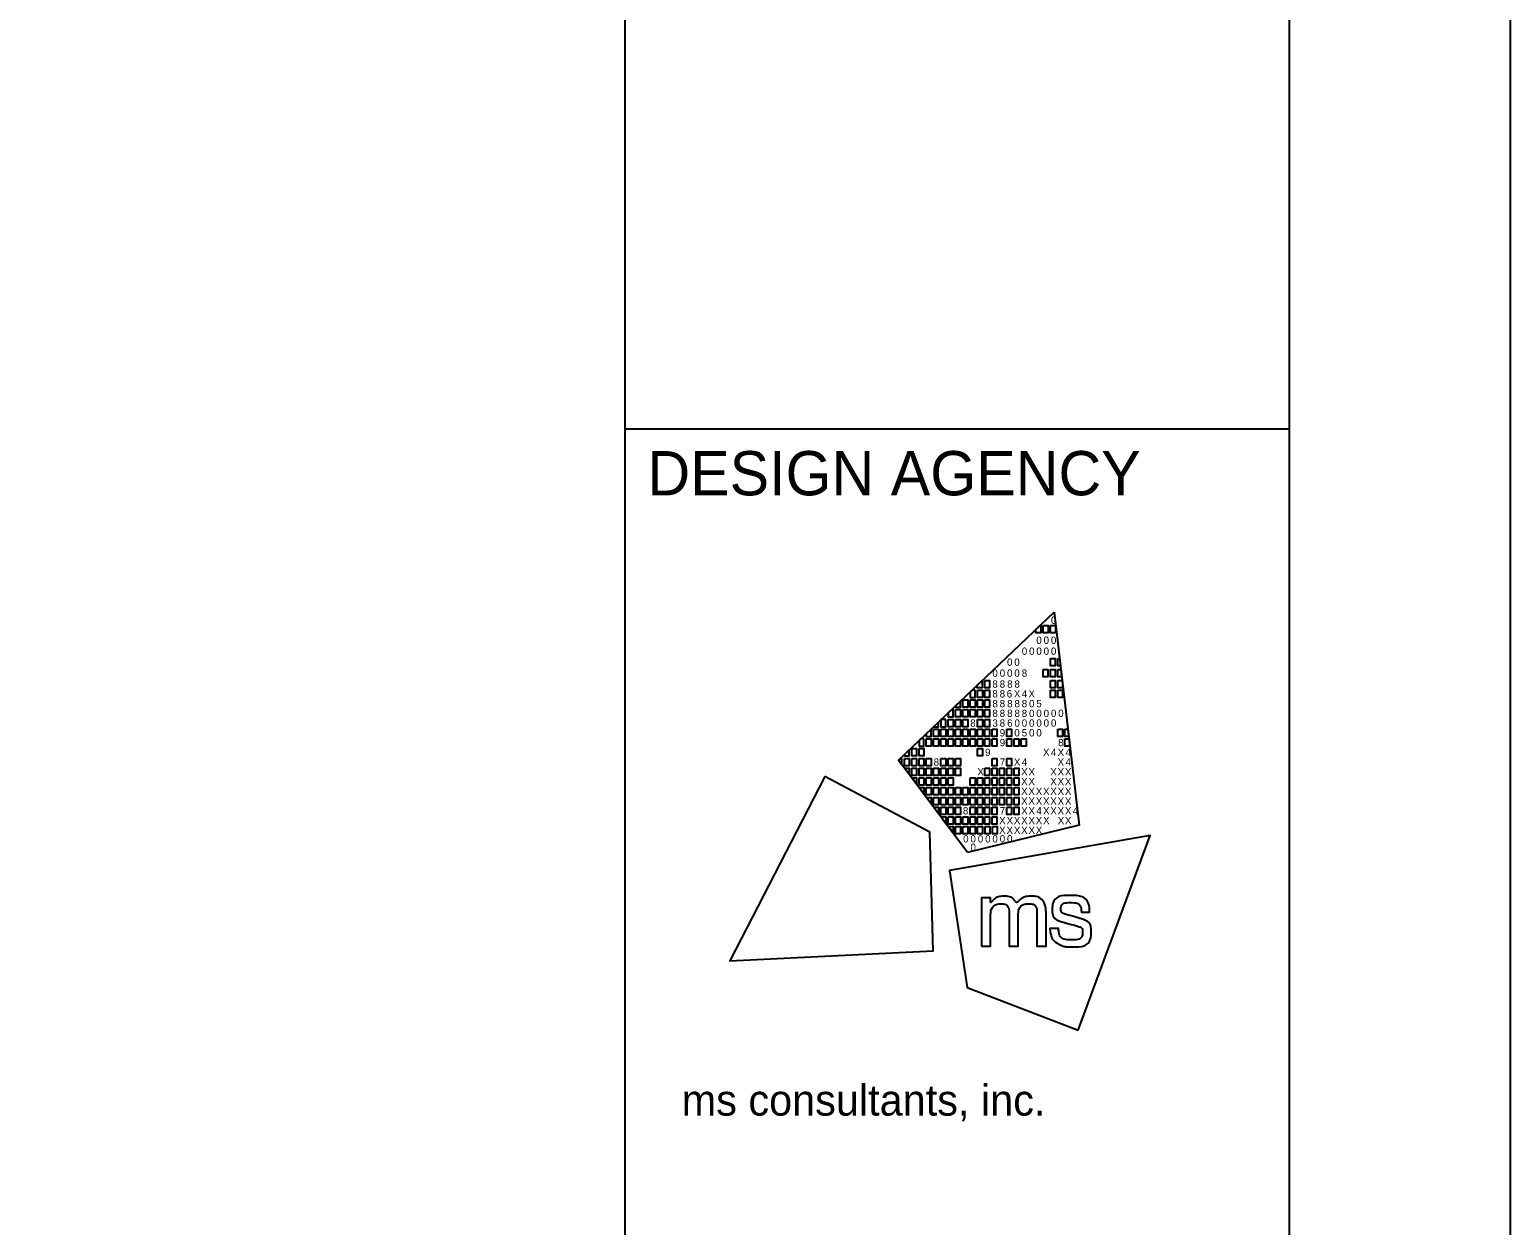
# Model space of a CAD drawing. Extents: x 0 to 680, y 0 to 440.
# Drawn here: x 613.1 to 680, y 54 to 108 of the extents above; entities that cross this region are included whole.
import ezdxf

# ---------------------------------------------------------------- set-up
doc = ezdxf.new("R2010")
doc.units = 0
for name, color, linetype in [('Default', 7, 'Continuous'), ('SH_Border', 7, 'Continuous'), ('SH_Cut_Line', 7, 'Continuous'), ('SH_Data', 7, 'Continuous')]:
    doc.layers.add(name, color=color, linetype=linetype)

msp = doc.modelspace()

# ---------------------------------------------------------------- linework, layer by layer
at = {"layer": 'Default'}
for p, q in [((652.351, 75.039), (659.376, 81.722)), ((659.376, 81.722), (659.376, 81.722)), ((659.376, 81.722), (660.506, 72.103)), ((655.461, 70.86), (652.351, 75.039)), ((660.506, 72.103), (655.461, 70.86))]:
    msp.add_line(p, q, dxfattribs=at)
for points in [[(658.559, 80.945), (658.738, 81.116), (658.779, 81.116), (658.779, 80.785), (658.559, 80.785)], [(658.888, 81.116), (659.109, 81.116), (659.109, 80.785), (658.888, 80.785)], [(659.219, 81.116), (659.439, 81.116), (659.439, 80.785), (659.219, 80.785)], [(658.883, 79.134), (659.103, 79.134), (659.103, 78.804), (658.883, 78.804)], [(659.212, 79.629), (659.433, 79.629), (659.433, 79.299), (659.212, 79.299)], [(659.212, 79.134), (659.433, 79.134), (659.433, 78.804), (659.212, 78.804)], [(659.542, 79.629), (659.622, 79.629), (659.661, 79.299), (659.542, 79.299)], [(659.542, 79.134), (659.68, 79.134), (659.719, 78.804), (659.542, 78.804)], [(655.908, 78.422), (656.128, 78.632), (656.128, 78.308), (655.908, 78.308)], [(656.246, 78.639), (656.466, 78.639), (656.466, 78.308), (656.246, 78.308)], [(659.212, 78.639), (659.433, 78.639), (659.433, 78.308), (659.212, 78.308)], [(659.542, 78.639), (659.738, 78.639), (659.762, 78.437), (659.762, 78.308), (659.542, 78.308)], [(655.255, 77.758), (655.476, 77.758), (655.476, 77.428), (655.255, 77.428)], [(655.586, 77.758), (655.806, 77.758), (655.806, 77.428), (655.586, 77.428)], [(655.916, 78.198), (656.136, 78.198), (656.136, 77.868), (655.916, 77.868)], [(655.916, 77.758), (656.136, 77.758), (656.136, 77.428), (655.916, 77.428)], [(656.246, 78.198), (656.466, 78.198), (656.466, 77.868), (656.246, 77.868)], [(656.246, 77.758), (656.466, 77.758), (656.466, 77.428), (656.246, 77.428)], [(659.212, 78.198), (659.433, 78.198), (659.433, 77.868), (659.212, 77.868)], [(659.542, 78.198), (659.762, 78.198), (659.762, 77.868), (659.542, 77.868)], [(654.925, 77.318), (655.145, 77.318), (655.145, 76.987), (654.925, 76.987)], [(655.255, 77.318), (655.476, 77.318), (655.476, 76.987), (655.255, 76.987)], [(655.586, 77.318), (655.806, 77.318), (655.806, 76.987), (655.586, 76.987)], [(655.916, 77.318), (656.136, 77.318), (656.136, 76.987), (655.916, 76.987)], [(656.246, 77.318), (656.466, 77.318), (656.466, 76.987), (656.246, 76.987)], [(653.934, 76.437), (654.154, 76.437), (654.154, 76.107), (653.934, 76.107)], [(654.265, 76.437), (654.485, 76.437), (654.485, 76.107), (654.265, 76.107)], [(654.595, 76.877), (654.815, 76.877), (654.815, 76.547), (654.595, 76.547)], [(654.595, 76.437), (654.815, 76.437), (654.815, 76.107), (654.595, 76.107)], [(654.925, 76.877), (655.145, 76.877), (655.145, 76.547), (654.925, 76.547)], [(654.925, 76.437), (655.145, 76.437), (655.145, 76.107), (654.925, 76.107)], [(655.255, 76.877), (655.476, 76.877), (655.476, 76.547), (655.255, 76.547)], [(655.255, 76.437), (655.476, 76.437), (655.476, 76.107), (655.255, 76.107)], [(655.586, 76.437), (655.806, 76.437), (655.806, 76.107), (655.586, 76.107)], [(655.916, 76.877), (656.136, 76.877), (656.136, 76.547), (655.916, 76.547)], [(655.916, 76.437), (656.136, 76.437), (656.136, 76.107), (655.916, 76.107)], [(656.246, 76.877), (656.466, 76.877), (656.466, 76.547), (656.246, 76.547)], [(656.246, 76.437), (656.466, 76.437), (656.466, 76.107), (656.246, 76.107)], [(656.576, 76.437), (656.797, 76.437), (656.797, 76.107), (656.576, 76.107)], [(657.237, 76.437), (657.457, 76.437), (657.457, 76.107), (657.237, 76.107)], [(659.542, 76.437), (659.762, 76.437), (659.762, 76.107), (659.542, 76.107)], [(659.871, 76.437), (659.997, 76.437), (660.036, 76.107), (659.871, 76.107)], [(653.604, 75.996), (653.824, 75.996), (653.824, 75.666), (653.604, 75.666)], [(653.934, 75.996), (654.154, 75.996), (654.154, 75.666), (653.934, 75.666)], [(654.265, 75.996), (654.485, 75.996), (654.485, 75.666), (654.265, 75.666)], [(654.595, 75.996), (654.815, 75.996), (654.815, 75.666), (654.595, 75.666)], [(654.925, 75.996), (655.145, 75.996), (655.145, 75.666), (654.925, 75.666)], [(655.255, 75.996), (655.476, 75.996), (655.476, 75.666), (655.255, 75.666)], [(655.586, 75.996), (655.806, 75.996), (655.806, 75.666), (655.586, 75.666)], [(655.916, 75.996), (656.136, 75.996), (656.136, 75.666), (655.916, 75.666)], [(656.246, 75.996), (656.466, 75.996), (656.466, 75.666), (656.246, 75.666)], [(656.576, 75.996), (656.797, 75.996), (656.797, 75.666), (656.576, 75.666)], [(657.237, 75.996), (657.457, 75.996), (657.457, 75.666), (657.237, 75.666)], [(657.567, 75.996), (657.787, 75.996), (657.787, 75.666), (657.567, 75.666)], [(657.895, 75.996), (658.115, 75.996), (658.115, 75.666), (657.895, 75.666)], [(659.871, 75.996), (660.049, 75.996), (660.088, 75.666), (659.871, 75.666)], [(652.613, 75.116), (652.833, 75.116), (652.833, 74.785), (652.613, 74.785)], [(652.943, 75.556), (653.164, 75.556), (653.164, 75.226), (652.943, 75.226)], [(652.943, 75.116), (653.164, 75.116), (653.164, 74.785), (652.943, 74.785)], [(653.274, 75.556), (653.494, 75.556), (653.494, 75.226), (653.274, 75.226)], [(653.274, 75.116), (653.494, 75.116), (653.494, 74.785), (653.274, 74.785)], [(653.604, 75.116), (653.824, 75.116), (653.824, 74.785), (653.604, 74.785)], [(654.265, 75.116), (654.485, 75.116), (654.485, 74.785), (654.265, 74.785)], [(654.595, 75.116), (654.815, 75.116), (654.815, 74.785), (654.595, 74.785)], [(654.925, 75.116), (655.145, 75.116), (655.145, 74.785), (654.925, 74.785)], [(655.916, 75.556), (656.136, 75.556), (656.136, 75.226), (655.916, 75.226)], [(656.576, 75.116), (656.797, 75.116), (656.797, 74.785), (656.576, 74.785)], [(657.237, 75.116), (657.457, 75.116), (657.457, 74.785), (657.237, 74.785)], [(652.613, 74.675), (652.833, 74.675), (652.833, 74.4)], [(652.943, 74.675), (653.164, 74.675), (653.164, 74.345), (652.943, 74.345)], [(653.274, 74.675), (653.494, 74.675), (653.494, 74.345), (653.274, 74.345)], [(653.604, 74.675), (653.824, 74.675), (653.824, 74.345), (653.604, 74.345)], [(653.934, 74.675), (654.154, 74.675), (654.154, 74.345), (653.934, 74.345)], [(654.265, 74.675), (654.485, 74.675), (654.485, 74.345), (654.265, 74.345)], [(654.595, 74.675), (654.815, 74.675), (654.815, 74.345), (654.595, 74.345)], [(654.925, 74.675), (655.145, 74.675), (655.145, 74.345), (654.925, 74.345)], [(656.246, 74.675), (656.466, 74.675), (656.466, 74.345), (656.246, 74.345)], [(656.576, 74.675), (656.797, 74.675), (656.797, 74.345), (656.576, 74.345)], [(656.907, 74.675), (657.127, 74.675), (657.127, 74.345), (656.907, 74.345)], [(657.237, 74.675), (657.457, 74.675), (657.457, 74.345), (657.237, 74.345)], [(657.567, 74.675), (657.787, 74.675), (657.787, 74.345), (657.567, 74.345)], [(652.943, 74.235), (653.164, 74.235), (653.164, 73.96)], [(653.274, 74.235), (653.494, 74.235), (653.494, 73.905), (653.274, 73.905)], [(653.274, 73.795), (653.494, 73.795), (653.494, 73.519)], [(653.494, 73.795), (653.494, 73.795), (653.494, 73.795)], [(653.604, 74.235), (653.824, 74.235), (653.824, 73.905), (653.604, 73.905)], [(653.604, 73.795), (653.824, 73.795), (653.824, 73.464), (653.604, 73.464)], [(653.934, 74.235), (654.154, 74.235), (654.154, 73.905), (653.934, 73.905)], [(653.934, 73.795), (654.154, 73.795), (654.154, 73.464), (653.934, 73.464)], [(654.265, 74.235), (654.485, 74.235), (654.485, 73.905), (654.265, 73.905)], [(654.265, 73.795), (654.485, 73.795), (654.485, 73.464), (654.265, 73.464)], [(654.595, 74.235), (654.815, 74.235), (654.815, 73.905), (654.595, 73.905)], [(654.595, 73.795), (654.815, 73.795), (654.815, 73.464), (654.595, 73.464)], [(654.925, 73.795), (655.145, 73.795), (655.145, 73.464), (654.925, 73.464)], [(655.255, 73.795), (655.476, 73.795), (655.476, 73.464), (655.255, 73.464)], [(655.586, 74.235), (655.806, 74.235), (655.806, 73.905), (655.586, 73.905)], [(655.586, 73.795), (655.806, 73.795), (655.806, 73.464), (655.586, 73.464)], [(655.916, 74.235), (656.136, 74.235), (656.136, 73.905), (655.916, 73.905)], [(655.916, 73.795), (656.136, 73.795), (656.136, 73.464), (655.916, 73.464)], [(656.246, 74.235), (656.466, 74.235), (656.466, 73.905), (656.246, 73.905)], [(656.246, 73.795), (656.466, 73.795), (656.466, 73.464), (656.246, 73.464)], [(656.576, 74.235), (656.797, 74.235), (656.797, 73.905), (656.576, 73.905)], [(656.576, 73.795), (656.797, 73.795), (656.797, 73.464), (656.576, 73.464)], [(656.907, 74.235), (657.127, 74.235), (657.127, 73.905), (656.907, 73.905)], [(656.907, 73.795), (657.127, 73.795), (657.127, 73.464), (656.907, 73.464)], [(657.237, 74.235), (657.457, 74.235), (657.457, 73.905), (657.237, 73.905)], [(657.237, 73.795), (657.457, 73.795), (657.457, 73.464), (657.237, 73.464)], [(657.567, 74.235), (657.787, 74.235), (657.787, 73.905), (657.567, 73.905)], [(657.567, 73.795), (657.787, 73.795), (657.787, 73.464), (657.567, 73.464)], [(653.604, 73.354), (653.824, 73.354), (653.824, 73.079)], [(653.934, 73.354), (654.154, 73.354), (654.154, 73.024), (653.934, 73.024)], [(654.265, 73.354), (654.485, 73.354), (654.485, 73.024), (654.265, 73.024)], [(654.595, 73.354), (654.815, 73.354), (654.815, 73.024), (654.595, 73.024)], [(654.925, 73.354), (655.145, 73.354), (655.145, 73.024), (654.925, 73.024)], [(655.255, 73.354), (655.476, 73.354), (655.476, 73.024), (655.255, 73.024)], [(655.586, 73.354), (655.806, 73.354), (655.806, 73.024), (655.586, 73.024)], [(655.916, 73.354), (656.136, 73.354), (656.136, 73.024), (655.916, 73.024)], [(656.246, 73.354), (656.466, 73.354), (656.466, 73.024), (656.246, 73.024)], [(656.576, 73.354), (656.797, 73.354), (656.797, 73.024), (656.576, 73.024)], [(656.907, 73.354), (657.127, 73.354), (657.127, 73.024), (656.907, 73.024)], [(657.237, 73.354), (657.457, 73.354), (657.457, 73.024), (657.237, 73.024)], [(657.567, 73.354), (657.787, 73.354), (657.787, 73.024), (657.567, 73.024)], [(654.155, 72.611), (653.931, 72.915), (654.155, 72.915)], [(654.48, 72.164), (654.264, 72.474), (654.484, 72.474)], [(654.265, 72.914), (654.485, 72.914), (654.485, 72.584), (654.265, 72.584)], [(654.595, 72.914), (654.815, 72.914), (654.815, 72.584), (654.595, 72.584)], [(654.595, 72.473), (654.815, 72.473), (654.815, 72.143), (654.595, 72.143)], [(654.925, 72.914), (655.145, 72.914), (655.145, 72.584), (654.925, 72.584)], [(654.925, 72.473), (655.145, 72.473), (655.145, 72.143), (654.925, 72.143)], [(655.255, 72.473), (655.476, 72.473), (655.476, 72.143), (655.255, 72.143)], [(655.586, 72.914), (655.806, 72.914), (655.806, 72.584), (655.586, 72.584)], [(655.586, 72.473), (655.806, 72.473), (655.806, 72.143), (655.586, 72.143)], [(655.916, 72.914), (656.136, 72.914), (656.136, 72.584), (655.916, 72.584)], [(655.916, 72.473), (656.136, 72.473), (656.136, 72.143), (655.916, 72.143)], [(656.246, 72.914), (656.466, 72.914), (656.466, 72.584), (656.246, 72.584)], [(656.246, 72.473), (656.466, 72.473), (656.466, 72.143), (656.246, 72.143)], [(656.576, 72.914), (656.797, 72.914), (656.797, 72.584), (656.576, 72.584)], [(656.576, 72.473), (656.797, 72.473), (656.797, 72.143), (656.576, 72.143)], [(657.237, 72.914), (657.457, 72.914), (657.457, 72.584), (657.237, 72.584)], [(657.567, 72.914), (657.787, 72.914), (657.787, 72.584), (657.567, 72.584)], [(654.605, 72.034), (654.815, 72.034), (654.816, 71.75)], [(654.927, 72.034), (655.147, 72.034), (655.147, 71.704), (654.927, 71.704)], [(655.26, 72.034), (655.48, 72.034), (655.48, 71.704), (655.26, 71.704)], [(655.588, 72.034), (655.808, 72.034), (655.808, 71.704), (655.588, 71.704)], [(655.921, 72.034), (656.141, 72.034), (656.141, 71.704), (655.921, 71.704)], [(656.259, 72.033), (656.48, 72.033), (656.48, 71.703), (656.259, 71.703)], [(656.593, 72.033), (656.813, 72.033), (656.813, 71.703), (656.593, 71.703)]]:
    msp.add_lwpolyline(points, close=True, dxfattribs=at)
for points in [[(655.145, 77.697), (654.925, 77.488), (654.925, 77.428), (655.145, 77.428), (655.145, 77.697)], [(655.806, 78.198), (655.672, 78.198), (655.586, 78.116), (655.586, 77.868), (655.806, 77.868), (655.806, 78.198)], [(654.815, 77.383), (654.595, 77.173), (654.595, 76.987), (654.815, 76.987), (654.815, 77.383)], [(653.824, 76.44), (653.604, 76.231), (653.604, 76.107), (653.824, 76.107), (653.824, 76.44)], [(654.154, 76.754), (653.936, 76.547), (654.154, 76.547), (654.154, 76.754)], [(654.485, 76.877), (654.284, 76.877), (654.265, 76.859), (654.265, 76.547), (654.485, 76.547), (654.485, 76.877)], [(653.494, 75.996), (653.358, 75.996), (653.274, 75.916), (653.274, 75.666), (653.494, 75.666), (653.494, 75.996)], [(652.503, 75.116), (652.432, 75.116), (652.351, 75.039), (652.503, 74.835), (652.503, 75.116)], [(652.833, 75.497), (652.613, 75.288), (652.613, 75.226), (652.833, 75.226), (652.833, 75.497)], [(649.025, 74.297), (644.719, 65.976), (653.913, 66.429), (653.768, 71.783), (649.025, 74.297)], [(660.459, 62.844), (663.718, 71.628), (654.648, 70.058), (655.444, 64.762), (660.459, 62.844)]]:
    msp.add_lwpolyline(points, dxfattribs=at)
for points in [[(656.096, 66.63), (656.096, 66.63), (656.096, 68.818), (656.096, 68.818), (656.096, 68.818), (656.51, 68.818), (656.51, 68.818), (656.51, 68.818), (656.51, 68.595), (656.51, 68.595), (656.692, 68.799), (656.914, 68.889), (657.111, 68.889), (657.377, 68.889), (657.583, 68.744), (657.674, 68.533), (657.83, 68.761), (658.101, 68.892), (658.332, 68.892), (658.651, 68.892), (658.902, 68.7), (658.988, 68.425), (658.989, 68.425), (658.989, 68.424), (658.989, 68.423), (659.003, 68.379), (659.013, 68.345), (659.013, 68.141), (659.013, 68.141), (659.013, 66.629), (659.013, 66.629), (659.013, 66.629), (658.606, 66.629), (658.606, 66.629), (658.606, 66.629), (658.606, 68.096), (658.606, 68.096), (658.606, 68.402), (658.438, 68.548), (658.221, 68.548), (657.991, 68.548), (657.759, 68.341), (657.759, 68.003), (657.759, 68.003), (657.759, 66.63), (657.759, 66.63), (657.759, 66.63), (657.349, 66.63), (657.349, 66.63), (657.349, 66.63), (657.349, 68.118), (657.349, 68.118), (657.349, 68.406), (657.177, 68.548), (656.993, 68.548), (656.768, 68.548), (656.508, 68.341), (656.508, 67.924), (656.508, 67.924), (656.508, 66.63), (656.508, 66.63), (656.508, 66.63), (656.096, 66.63), (656.096, 66.63)], [(659.192, 67.417), (659.192, 67.417), (659.19, 67.434), (659.19, 67.434), (659.19, 67.434), (659.207, 67.434), (659.207, 67.434), (659.207, 67.434), (659.566, 67.434), (659.566, 67.434), (659.566, 67.434), (659.579, 67.434), (659.579, 67.434), (659.579, 67.434), (659.58, 67.42), (659.58, 67.42), (659.606, 67.108), (659.774, 66.92), (660.18, 66.92), (660.546, 66.92), (660.667, 67.109), (660.667, 67.262), (660.667, 67.463), (660.512, 67.515), (660.351, 67.561), (660.351, 67.561), (659.74, 67.734), (659.74, 67.734), (659.441, 67.818), (659.296, 68.037), (659.296, 68.285), (659.296, 68.606), (659.536, 68.923), (660.105, 68.923), (660.697, 68.923), (660.979, 68.57), (660.979, 68.189), (660.979, 68.189), (660.979, 68.174), (660.979, 68.174), (660.979, 68.174), (660.964, 68.174), (660.964, 68.174), (660.964, 68.174), (660.625, 68.174), (660.625, 68.174), (660.625, 68.174), (660.611, 68.174), (660.611, 68.174), (660.611, 68.174), (660.61, 68.189), (660.61, 68.189), (660.604, 68.416), (660.454, 68.599), (660.112, 68.599), (659.782, 68.599), (659.686, 68.435), (659.686, 68.314), (659.686, 68.216), (659.738, 68.118), (659.918, 68.067), (659.918, 68.067), (660.51, 67.897), (660.51, 67.897), (660.925, 67.777), (661.054, 67.555), (661.054, 67.279), (661.054, 66.925), (660.82, 66.597), (660.175, 66.597), (659.904, 66.597), (659.754, 66.642), (659.646, 66.696), (659.381, 66.829), (659.219, 67.072), (659.192, 67.417)]]:
    msp.add_open_spline(points, degree=3, dxfattribs=at)
at = {"layer": 'SH_Border'}
for p, q in [((640, 10), (640, 430)), ((640, 90), (670, 90))]:
    msp.add_line(p, q, dxfattribs=at)
msp.add_lwpolyline([(30, 430), (670, 430), (670, 10), (30, 10)], close=True, dxfattribs=at)
at = {"layer": 'SH_Cut_Line'}
msp.add_lwpolyline([(0, 0), (680, 0), (680, 440), (0, 440)], close=True, dxfattribs=at)
at = {"layer": 'SH_Data'}
msp.add_line((655, 70), (655, 70), dxfattribs=at)

# ---------------------------------------------------------------- texts
at = {"layer": 'Default'}
for s, p in [('0', (659.235, 81.194)), ('0', (658.576, 80.29)), ('0', (658.905, 80.29)), ('0', (659.235, 80.29)), ('0', (657.917, 79.795)), ('0', (658.246, 79.795)), ('0', (658.576, 79.795)), ('0', (658.905, 79.795)), ('0', (659.235, 79.795)), ('0', (656.59, 78.804)), ('0', (656.921, 78.804)), ('0', (657.251, 79.299)), ('0', (657.251, 78.804)), ('0', (657.581, 79.299)), ('0', (657.581, 78.804)), ('8', (657.916, 78.804)), ('8', (656.59, 78.308)), ('8', (656.92, 78.308)), ('8', (657.257, 78.308)), ('8', (657.587, 78.308)), ('8', (656.59, 77.868)), ('8', (656.59, 77.426)), ('8', (656.92, 77.868)), ('8', (656.92, 77.426)), ('6', (657.237, 77.868)), ('8', (657.257, 77.426)), ('X', (657.562, 77.868)), ('8', (657.588, 77.426)), ('4', (657.917, 77.868)), ('8', (657.916, 77.426)), ('X', (658.22, 77.868)), ('0', (658.246, 77.426)), ('5', (658.574, 77.426)), ('8', (656.59, 76.987)), ('8', (656.92, 76.987)), ('8', (657.257, 76.987)), ('8', (657.588, 76.987)), ('8', (657.916, 76.987)), ('0', (658.246, 76.987)), ('0', (658.576, 76.987)), ('0', (658.905, 76.987)), ('0', (659.235, 76.987)), ('0', (659.564, 76.987)), ('8', (655.586, 76.547)), ('3', (656.59, 76.547)), ('8', (656.92, 76.547)), ('9', (656.921, 76.107)), ('6', (657.258, 76.547)), ('0', (657.581, 76.107)), ('0', (657.588, 76.547)), ('5', (657.916, 76.107)), ('0', (657.917, 76.547)), ('0', (658.246, 76.547)), ('0', (658.246, 76.107)), ('0', (658.576, 76.547)), ('0', (658.576, 76.107)), ('0', (658.905, 76.547)), ('0', (659.235, 76.547)), ('9', (656.921, 75.666)), ('8', (659.563, 75.666)), ('8', (653.934, 74.785)), ('9', (656.26, 75.226)), ('7', (656.921, 74.785)), ('X', (657.562, 74.785)), ('4', (657.917, 74.785)), ('X', (658.879, 75.226)), ('4', (659.234, 75.226)), ('X', (659.538, 75.226)), ('X', (659.538, 74.785)), ('4', (659.893, 75.226)), ('4', (659.893, 74.785)), ('X', (655.911, 74.345)), ('X', (657.891, 74.345)), ('X', (658.22, 74.345)), ('X', (659.208, 74.345)), ('X', (659.538, 74.345)), ('X', (659.867, 74.345)), ('X', (657.891, 73.905)), ('X', (657.891, 73.464)), ('X', (658.22, 73.905)), ('X', (658.22, 73.464)), ('X', (658.549, 73.464)), ('X', (658.879, 73.464)), ('X', (659.208, 73.905)), ('X', (659.208, 73.464)), ('X', (659.538, 73.905)), ('X', (659.538, 73.464)), ('X', (659.867, 73.905)), ('X', (659.867, 73.464)), ('X', (657.891, 73.024)), ('X', (658.22, 73.024)), ('X', (658.549, 73.024)), ('X', (658.879, 73.024)), ('X', (659.208, 73.024)), ('X', (659.538, 73.024)), ('X', (659.867, 73.024)), ('8', (655.255, 72.584)), ('X', (656.894, 72.143)), ('7', (656.921, 72.584)), ('X', (657.232, 72.143)), ('X', (657.561, 72.143)), ('X', (657.891, 72.584)), ('X', (657.891, 72.143)), ('X', (658.22, 72.584)), ('X', (658.22, 72.143)), ('X', (658.549, 72.143)), ('4', (658.576, 72.584)), ('X', (658.879, 72.584)), ('X', (658.879, 72.143)), ('X', (659.208, 72.584)), ('X', (659.538, 72.584)), ('X', (659.544, 72.143)), ('X', (659.867, 72.584)), ('X', (659.867, 72.143)), ('4', (660.223, 72.584)), ('0', (655.269, 71.318)), ('0', (655.599, 71.318)), ('0', (655.93, 71.318)), ('0', (656.26, 71.318)), ('0', (656.59, 71.318)), ('X', (656.894, 71.703)), ('0', (656.921, 71.318)), ('X', (657.232, 71.703)), ('0', (657.251, 71.318)), ('X', (657.561, 71.703)), ('X', (657.891, 71.703)), ('X', (658.22, 71.703)), ('X', (658.549, 71.703)), ('0', (655.599, 70.933))]:
    msp.add_text(s, height=0.33, rotation=360, dxfattribs=at).set_placement(p)
at = {"layer": 'SH_Border'}
msp.add_text('ms consultants, inc.', height=1.4, rotation=360, dxfattribs=at).set_placement((642.547, 58.978))
at = {"layer": 'SH_Data'}
msp.add_text('DESIGN AGENCY', height=2, dxfattribs=at).set_placement((641, 87))

doc.saveas('drawing.dxf')
